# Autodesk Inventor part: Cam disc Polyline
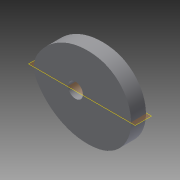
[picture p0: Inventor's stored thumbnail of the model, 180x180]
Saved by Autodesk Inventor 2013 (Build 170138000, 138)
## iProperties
Created: 2008-06
Part Number: Cam disc Polyline
Document SubType Name: Modeling
Designer: tangg
Density: 1 g/cm^3
Mass: 6.8214 g
Surface Area: 30.2978 cm^2
Volume: 6.8214 cm^3
Material: Generic
Author: tangg
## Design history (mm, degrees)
sketch "Sketch6"
  geometry: L1 (-27.024, 0)-(35.639, 0) reference; L2 (0, -29.269)-(0, 29.269) reference; C1 r 3.175 at (0, 0); A1 r 10.048 centre (-7.62, 0) between (-16.236, 5.17) and (-16.236, -5.17); A2 r 24.859 centre (5.08, -7.62) between (9.955, 16.756) and (-16.236, 5.17); A3 r 17.088 centre (6.604, 0) between (9.955, -16.756) and (9.955, 16.756); A4 r 10.048 centre (-7.62, 0) between (-16.236, 5.17) and (-16.236, -5.17); A5 r 24.859 centre (5.08, 7.62) between (-16.236, -5.17) and (9.955, -16.756); A6 r 17.088 centre (6.604, 0) between (9.955, -16.756) and (23.692, 0)
  constraints: 13 point on circle, 7 centre point, 5 symmetric about line, 4 tangent, 2 point on line, 1 midpoint, 3 other
  dimensions: "d11" = 7.62 distance from line of L1 A5.centre; "d12" = 5.08 distance from line of L2 A5.centre; "d13" = 6.35 diameter of C1; "d16" = 6.604 distance from line of L2 A3.centre; "d17" = 7.62 distance from line of L2 A1.centre
extrude "Extrusion2" new body sketch "Sketch6" distance "d14" = 6.35; taper "d15" = 0 deg
body "Solid1"
